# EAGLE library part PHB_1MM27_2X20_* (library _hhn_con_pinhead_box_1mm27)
Pin Header Box-Type, 1.27mm/0.5"/50mil Pitch, 2x20 Circuits Note: see library description for an important note about THT-version
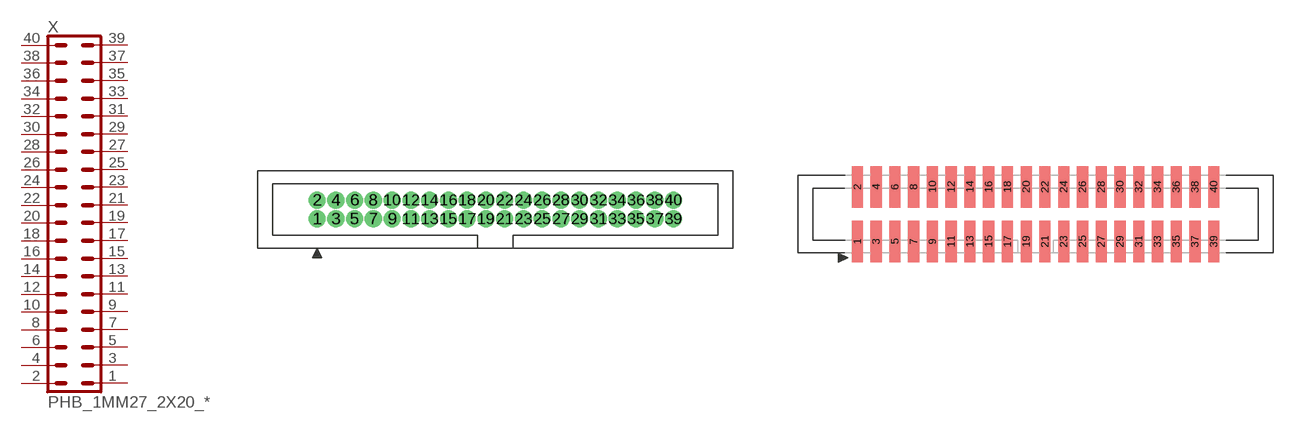
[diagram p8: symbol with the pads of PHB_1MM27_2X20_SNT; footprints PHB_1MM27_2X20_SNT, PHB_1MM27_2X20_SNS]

Designator prefix X

## PHB_1MM27_2X20_SNT  [PHB_1MM27_2X20_SNT]
1  1  pas
2  2  pas
3  3  pas
4  4  pas
5  5  pas
6  6  pas
7  7  pas
8  8  pas
9  9  pas
10  10  pas
11  11  pas
12  12  pas
13  13  pas
14  14  pas
15  15  pas
16  16  pas
17  17  pas
18  18  pas
19  19  pas
20  20  pas
21  21  pas
22  22  pas
23  23  pas
24  24  pas
25  25  pas
26  26  pas
27  27  pas
28  28  pas
29  29  pas
30  30  pas
31  31  pas
32  32  pas
33  33  pas
34  34  pas
35  35  pas
36  36  pas
37  37  pas
38  38  pas
39  39  pas
40  40  pas

## PHB_1MM27_2X20_SNS  [PHB_1MM27_2X20_SNS]
Pads as for PHB_1MM27_2X20_SNT

## Footprint PHB_1MM27_2X20_SNT (pad centres in mm)
Pin Header Box-Type, 1.27mm Pitch, 2x20 circuits, Straight, No Locking, THT Important Note: Diameter in this lbr is set to a specific value (NOT 'auto' = 0), this is ignored by actual eagle versions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
drill 0.65 pad 1 round: 1 -12.065,-0.635; 2 -12.065,0.635; 3 -10.795,-0.635; 4 -10.795,0.635; 5 -9.525,-0.635; 6 -9.525,0.635; 7 -8.255,-0.635; 8 -8.255,0.635; 9 -6.985,-0.635; 10 -6.985,0.635; 11 -5.715,-0.635; 12 -5.715,0.635; 13 -4.445,-0.635; 14 -4.445,0.635; 15 -3.175,-0.635; 16 -3.175,0.635; 17 -1.905,-0.635; 18 -1.905,0.635; 19 -0.635,-0.635; 20 -0.635,0.635; 21 0.635,-0.635; 22 0.635,0.635; 23 1.905,-0.635; 24 1.905,0.635; 25 3.175,-0.635; 26 3.175,0.635; 27 4.445,-0.635; 28 4.445,0.635; 29 5.715,-0.635; 30 5.715,0.635; 31 6.985,-0.635; 32 6.985,0.635; 33 8.255,-0.635; 34 8.255,0.635; 35 9.525,-0.635; 36 9.525,0.635; 37 10.795,-0.635; 38 10.795,0.635; 39 12.065,-0.635; 40 12.065,0.635

## Footprint PHB_1MM27_2X20_SNS (pad centres in mm)
Pin Header Box-Type, 1.27mm Pitch, 2x20 circuits, Straight, No Locking, SMT
smd 0.76 x 2.8: 1 -12.065,-1.85; 2 -12.065,1.85; 3 -10.795,-1.85; 4 -10.795,1.85; 5 -9.525,-1.85; 6 -9.525,1.85; 7 -8.255,-1.85; 8 -8.255,1.85; 9 -6.985,-1.85; 10 -6.985,1.85; 11 -5.715,-1.85; 12 -5.715,1.85; 13 -4.445,-1.85; 14 -4.445,1.85; 15 -3.175,-1.85; 16 -3.175,1.85; 17 -1.905,-1.85; 18 -1.905,1.85; 19 -0.635,-1.85; 20 -0.635,1.85; 21 0.635,-1.85; 22 0.635,1.85; 23 1.905,-1.85; 24 1.905,1.85; 25 3.175,-1.85; 26 3.175,1.85; 27 4.445,-1.85; 28 4.445,1.85; 29 5.715,-1.85; 30 5.715,1.85; 31 6.985,-1.85; 32 6.985,1.85; 33 8.255,-1.85; 34 8.255,1.85; 35 9.525,-1.85; 36 9.525,1.85; 37 10.795,-1.85; 38 10.795,1.85; 39 12.065,-1.85; 40 12.065,1.85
